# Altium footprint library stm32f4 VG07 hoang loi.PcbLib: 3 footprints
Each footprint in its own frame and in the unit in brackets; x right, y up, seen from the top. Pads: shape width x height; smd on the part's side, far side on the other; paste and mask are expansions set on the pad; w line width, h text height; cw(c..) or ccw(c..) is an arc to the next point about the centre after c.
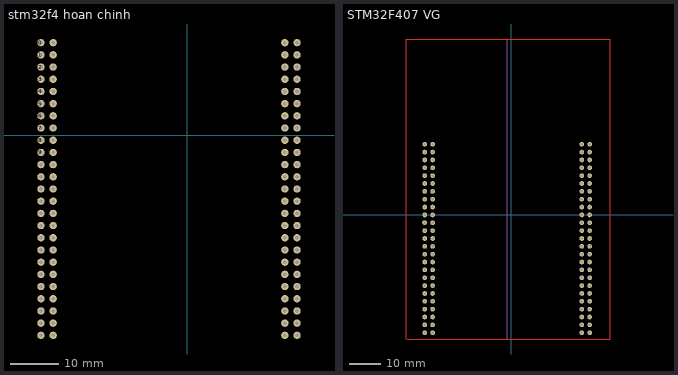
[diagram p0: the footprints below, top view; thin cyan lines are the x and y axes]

## stm32f4 hoan chinh [mil] "stm32f4 created by Hoang loi"
pads (100):
  round 60 hole 30: 0(-1200,760) 1(-1200,660) 2(-1200,560) 3(-1200,460) 4(-1200,360) 5(-1200,260) 6(-1200,160) 7(-1200,60) 8(-1200,-40) 9(-1200,-140) 10(-1200,-240) 11(-1200,-340) 12(-1200,-440) 13(-1200,-540) 14(-1200,-640) 15(-1200,-740) 16(-1200,-840) 17(-1200,-940) 18(-1200,-1040) 19(-1200,-1140) 20(-1200,-1240) 21(-1200,-1340) 22(-1200,-1440) 23(-1200,-1540) 24(-1200,-1640) 25(-1100,-1640) 26(-1100,-1540) 27(-1100,-1440) 28(-1100,-1340) 29(-1100,-1240) 30(-1100,-1140) 31(-1100,-1040) 32(-1100,-940) 33(-1100,-840) 34(-1100,-740) 35(-1100,-640) 36(-1100,-540) 37(-1100,-440) 38(-1100,-340) 39(-1100,-240) 40(-1100,-140) 41(-1100,-40) 42(-1100,60) 43(-1100,160) 44(-1100,260) 45(-1100,360) 46(-1100,460) 47(-1100,560) 48(-1100,660) 49(-1100,760) 50(800,760) 51(800,660) 53(800,460) 54(800,360) 55(800,260) 56(800,160) 57(800,60) 58(800,-40) 59(800,-140) 60(800,-240) 61(800,-340) 62(800,-440) 63(800,-540) 64(800,-640) 65(800,-740) 66(800,-840) 67(800,-940) 68(800,-1040) 69(800,-1140) 70(800,-1240) 71(800,-1340) 72(800,-1440) 73(800,-1540) 74(800,-1640) 75(900,-1640) 76(900,-1540) 77(900,-1440) 78(900,-1340) 79(900,-1240) 80(900,-1140) 81(900,-1040) 82(900,-940) 83(900,-840) 84(900,-740) 85(900,-640) 86(900,-540) 87(900,-440) 88(900,-340) 89(900,-240) 90(900,-140) 91(900,-40) 92(900,60) 93(900,160) 94(900,260) 95(900,360) 96(900,460) 97(900,560) 98(900,660) 99(900,760)
  round 60 hole 30 unplated: 52(800,560)
3D body: height 495.28, standoff 3.15, extent -1448.59,-1729.45 1149.83,2089.45

## STM32F407 VG [mil] "stm32f407 vg discovery"
pads (100):
  round 60 hole 30: 0(-1100,900) 1(-1100,800) 2(-1100,700) 3(-1100,600) 4(-1100,500) 5(-1100,400) 6(-1100,300) 7(-1100,200) 8(-1100,100) 9(-1100,0) 10(-1102.36,-98.43) 11(-1100,-200) 12(-1100,-300) 13(-1100,-400) 14(-1100,-500) 15(-1100,-600) 16(-1100,-700) 17(-1100,-800) 18(-1100,-900) 19(-1100,-1000) 20(-1100,-1100) 21(-1100,-1200) 22(-1100,-1300) 23(-1100,-1400) 24(-1100,-1500) 25(-1000,-1500) 26(-1000,-1400) 27(-1000,-1300) 28(-1000,-1200) 29(-1000,-1100) 30(-1000,-1000) 31(-1000,-900) 32(-1000,-800) 33(-1000,-700) 34(-1000,-600) 35(-1000,-500) 36(-1000,-400) 37(-1000,-300) 38(-1000,-200) 39(-1000,-100) 40(-1000,0) 41(-1000,100) 42(-1000,200) 43(-1000,300) 44(-1000,400) 45(-1000,500) 46(-1000,600) 47(-1000,700) 48(-1000,800) 49(-1000,900) 50(900,900) 51(900,800) 53(900,600) 54(900,500) 55(900,400) 56(900,300) 57(900,200) 58(900,100) 59(900,0) 60(900,-100) 61(900,-200) 62(900,-300) 63(900,-400) 64(900,-500) 65(900,-600) 66(900,-700) 67(900,-800) 68(900,-900) 69(900,-1000) 70(900,-1100) 71(900,-1200) 72(900,-1300) 73(900,-1400) 74(900,-1500) 75(1000,-1500) 76(1000,-1400) 77(1000,-1300) 78(1000,-1200) 79(1000,-1100) 80(1000,-1000) 81(1000,-900) 82(1000,-800) 83(1000,-700) 84(1000,-600) 85(1000,-500) 86(1000,-400) 87(1000,-300) 88(1000,-200) 89(1000,-100) 90(1000,0) 91(1000,100) 92(1000,200) 93(1000,300) 94(1000,400) 95(1000,500) 96(1000,600) 97(1000,700) 98(1000,800) 99(1000,900)
  round 60 hole 30 unplated: 52(900,700)
Top Layer:
  lines w10: -1340,2238.9 1260,2238.9 ; -1338.43,-1580 -1338.43,2238.9 ; -1320,-1580 1260,-1580 1260,2240
  text "STM32F407 VGx" at -420,740 h70
Mechanical 1:
  lines w10: -50,-1580 -50,2240
3D body: height 492.13, standoff 0, extent -1338.43,-1589.45 1260,2229.45

## STM324f footprint [mil]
